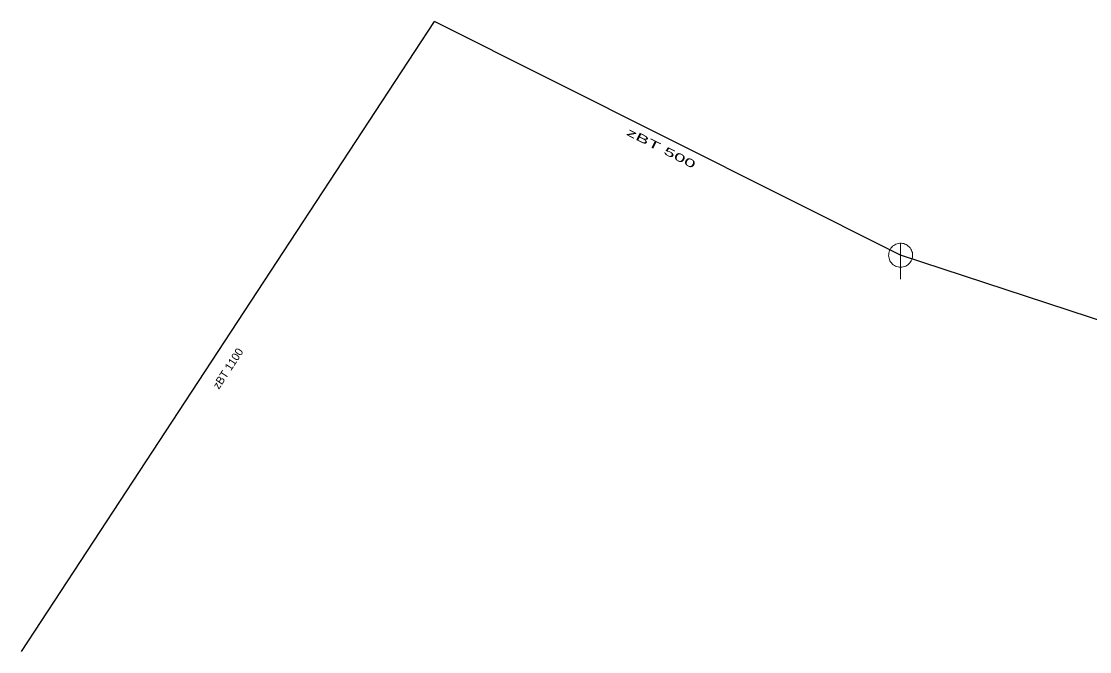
# Model space of a CAD drawing. Extents: x -688432 to -687974, y -973332 to -972704.
# Drawn here: x -688364.2 to -688275.2, y -972896.7 to -972844.1 of the extents above; entities that cross this region are included whole.
import ezdxf
from ezdxf.enums import TextEntityAlignment as Align

# ---------------------------------------------------------------- set-up
doc = ezdxf.new("R2010")
doc.units = 0
doc.header["$LTSCALE"] = 0.27
for name, color, linetype, lineweight in [('1', 7, 'Continuous', 25), ('14', 7, 'Continuous', 25), ('22', 7, 'Continuous', 13)]:
    doc.layers.add(name, color=color, linetype=linetype, lineweight=lineweight)

msp = doc.modelspace()

# ---------------------------------------------------------------- linework, layer by layer
at = {"layer": '14'}
for p in [(-688364.199, -972896.66), (-688290.938, -972863.596)]:
    msp.add_line(p, (-688329.767, -972844.085), dxfattribs=at)
msp.add_lwpolyline([(-688217.084, -972889.702), (-688227.642, -972884.745), (-688247.084, -972877.999), (-688290.938, -972863.596)], dxfattribs=at)
at = {"layer": '22'}
msp.add_line((-688290.938, -972865.596), (-688290.937, -972862.596), dxfattribs=at)
msp.add_lwpolyline([(-688289.938, -972863.596), (-688289.943, -972863.487), (-688289.961, -972863.379), (-688289.991, -972863.273), (-688290.031, -972863.172), (-688290.083, -972863.075), (-688290.145, -972862.985), (-688290.217, -972862.902), (-688290.297, -972862.828), (-688290.385, -972862.762), (-688290.479, -972862.707), (-688290.579, -972862.662), (-688290.684, -972862.629), (-688290.791, -972862.607), (-688290.9, -972862.597), (-688291.01, -972862.599), (-688291.118, -972862.613), (-688291.225, -972862.638), (-688291.328, -972862.675), (-688291.426, -972862.724), (-688291.518, -972862.782), (-688291.604, -972862.851), (-688291.681, -972862.928), (-688291.75, -972863.014), (-688291.809, -972863.106), (-688291.857, -972863.204), (-688291.894, -972863.307), (-688291.92, -972863.414), (-688291.934, -972863.522), (-688291.937, -972863.632), (-688291.927, -972863.741), (-688291.906, -972863.848), (-688291.872, -972863.952), (-688291.828, -972864.052), (-688291.773, -972864.147), (-688291.707, -972864.235), (-688291.633, -972864.315), (-688291.55, -972864.387), (-688291.46, -972864.449), (-688291.364, -972864.501), (-688291.262, -972864.542), (-688291.157, -972864.572), (-688291.049, -972864.59), (-688290.939, -972864.596), (-688290.83, -972864.59), (-688290.722, -972864.572), (-688290.617, -972864.543), (-688290.515, -972864.502), (-688290.418, -972864.45), (-688290.328, -972864.388), (-688290.245, -972864.317), (-688290.17, -972864.237), (-688290.105, -972864.149), (-688290.049, -972864.055), (-688290.005, -972863.955), (-688289.971, -972863.851), (-688289.949, -972863.743), (-688289.939, -972863.634)], close=True, dxfattribs=at)

# ---------------------------------------------------------------- texts
at = {"layer": '1', "width": 1.9}
msp.add_text('zBT 500 ', height=0.6667, rotation=333, dxfattribs=at).set_placement((-688310.8293, -972855.0659), align=Align.CENTER)
msp.add_text('zBT 500 ', height=0.6667, rotation=333, dxfattribs=at).set_placement((-688310.8293, -972855.0659), align=Align.CENTER)
msp.add_text('zBT 500 ', height=0.6667, rotation=333, dxfattribs=at).set_placement((-688310.8293, -972855.0659), align=Align.CENTER)
msp.add_text('zBT 500 ', height=0.6667, rotation=333, dxfattribs=at).set_placement((-688310.8293, -972855.0659), align=Align.CENTER)
msp.add_text('zBT 500 ', height=0.6667, rotation=333, dxfattribs=at).set_placement((-688310.8293, -972855.0659), align=Align.CENTER)
at = {"layer": '1'}
msp.add_text('zBT 1100', height=0.6667, rotation=57, dxfattribs=at).set_placement((-688346.704, -972873.2245), align=Align.CENTER)
msp.add_text('zBT 1100', height=0.6667, rotation=57, dxfattribs=at).set_placement((-688346.704, -972873.2245), align=Align.CENTER)
msp.add_text('zBT 1100', height=0.6667, rotation=57, dxfattribs=at).set_placement((-688346.704, -972873.2245), align=Align.CENTER)
msp.add_text('zBT 1100', height=0.6667, rotation=57, dxfattribs=at).set_placement((-688346.704, -972873.2245), align=Align.CENTER)
msp.add_text('zBT 1100', height=0.6667, rotation=57, dxfattribs=at).set_placement((-688346.704, -972873.2245), align=Align.CENTER)

doc.saveas('drawing.dxf')
